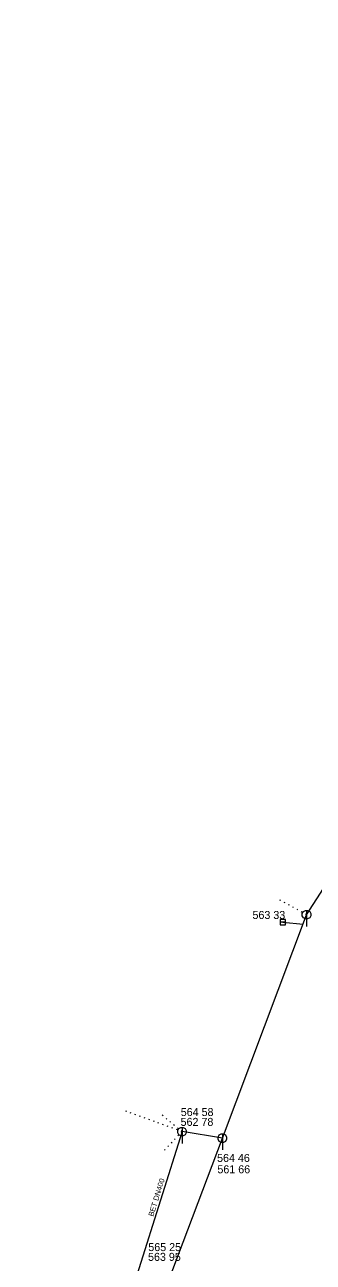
# Model space of a CAD drawing. Extents: x -710806 to -710046, y -1116920 to -1116046.
# Drawn here: x -710545.2 to -710518.2, y -1116694.3 to -1116578.3 of the extents above; entities that cross this region are included whole.
import ezdxf
from ezdxf.enums import TextEntityAlignment as Align

# ---------------------------------------------------------------- set-up
doc = ezdxf.new("R2010")
doc.units = 0
doc.header["$LTSCALE"] = 0.3
doc.linetypes.add('DOTTED', pattern=[1.5, 0.3, -1.2])
for name, color, linetype, lineweight in [('40', 7, 'Continuous', 13), ('41', 7, 'Continuous', 13), ('45', 7, 'DOTTED', 13)]:
    doc.layers.add(name, color=color, linetype=linetype, lineweight=lineweight)
doc.layers.add('43', color=7, linetype='Continuous')
doc.layers.add('44', color=7, linetype='Continuous')

msp = doc.modelspace()

# ---------------------------------------------------------------- linework, layer by layer
at = {"layer": '40'}
msp.add_line((-710526.717, -1116682.642), (-710518.824, -1116661.703), dxfattribs=at)
at = {"layer": '40', "linetype": 'DOTTED'}
msp.add_line((-710530.499, -1116682.028), (-710536.072, -1116679.999), dxfattribs=at)
at = {"layer": '40'}
for points in [[(-710518.824, -1116661.703), (-710489.738, -1116616.69), (-710468.921, -1116581.933), (-710476.116, -1116578.317)], [(-710545.241, -1116731.616), (-710526.717, -1116682.642), (-710530.499, -1116682.028), (-710534.547, -1116694.887), (-710539.549, -1116711.494), (-710545.154, -1116724.439)]]:
    msp.add_lwpolyline(points, dxfattribs=at)
at = {"layer": '41'}
for p, q in [((-710520.789, -1116662.168), (-710521.289, -1116662.168)), ((-710521.289, -1116662.168), (-710521.289, -1116662.668)), ((-710520.789, -1116662.668), (-710520.789, -1116662.168)), ((-710518.824, -1116661.303), (-710518.824, -1116662.803)), ((-710520.789, -1116662.418), (-710521.289, -1116662.418)), ((-710521.289, -1116662.668), (-710520.789, -1116662.668)), ((-710530.499, -1116681.628), (-710530.499, -1116683.128)), ((-710526.717, -1116682.242), (-710526.717, -1116683.742))]:
    msp.add_line(p, q, dxfattribs=at)
for points in [[(-710519.224, -1116661.803), (-710519.224, -1116661.603), (-710519.124, -1116661.403), (-710518.924, -1116661.303), (-710518.724, -1116661.303), (-710518.524, -1116661.403), (-710518.424, -1116661.603), (-710518.424, -1116661.803), (-710518.524, -1116662.003), (-710518.724, -1116662.103), (-710518.924, -1116662.103), (-710519.124, -1116662.003)], [(-710530.899, -1116682.128), (-710530.899, -1116681.928), (-710530.799, -1116681.728), (-710530.599, -1116681.628), (-710530.399, -1116681.628), (-710530.199, -1116681.728), (-710530.099, -1116681.928), (-710530.099, -1116682.128), (-710530.199, -1116682.328), (-710530.399, -1116682.428), (-710530.599, -1116682.428), (-710530.799, -1116682.328)], [(-710527.117, -1116682.742), (-710527.117, -1116682.542), (-710527.017, -1116682.342), (-710526.817, -1116682.242), (-710526.617, -1116682.242), (-710526.417, -1116682.342), (-710526.317, -1116682.542), (-710526.317, -1116682.742), (-710526.417, -1116682.942), (-710526.617, -1116683.042), (-710526.817, -1116683.042), (-710527.017, -1116682.942)]]:
    msp.add_lwpolyline(points, close=True, dxfattribs=at)
at = {"layer": '45'}
for p, q in [((-710518.824, -1116661.703), (-710521.558, -1116660.209)), ((-710530.499, -1116682.028), (-710532.451, -1116680.418)), ((-710530.499, -1116682.028), (-710532.32, -1116683.937))]:
    msp.add_line(p, q, dxfattribs=at)
at = {"layer": '45', "linetype": 'Continuous'}
msp.add_line((-710521.039, -1116662.418), (-710519.136, -1116662.605), dxfattribs=at)

# ---------------------------------------------------------------- texts
at = {"layer": '43'}
for s, p in [('563 33 ', (-710522.2192, -1116662.103)), ('564 58 ', (-710528.9432, -1116680.569)), ('564 46 ', (-710525.5382, -1116684.872)), ('565 25 ', (-710531.9842, -1116693.223))]:
    msp.add_text(s, height=0.75, dxfattribs=at).set_placement(p, align=Align.CENTER)
for s, p in [('562 78', (-710530.63, -1116681.492)), ('561 66', (-710527.18, -1116685.933)), ('563 95', (-710533.682, -1116694.139))]:
    msp.add_text(s, height=0.75, dxfattribs=at).set_placement(p)
at = {"layer": '44'}
msp.add_text('BET DN400', height=0.5, rotation=72.9, dxfattribs=at).set_placement((-710533.193, -1116690.022))

doc.saveas('drawing.dxf')
